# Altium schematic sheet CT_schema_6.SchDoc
size 364 x 245 mm
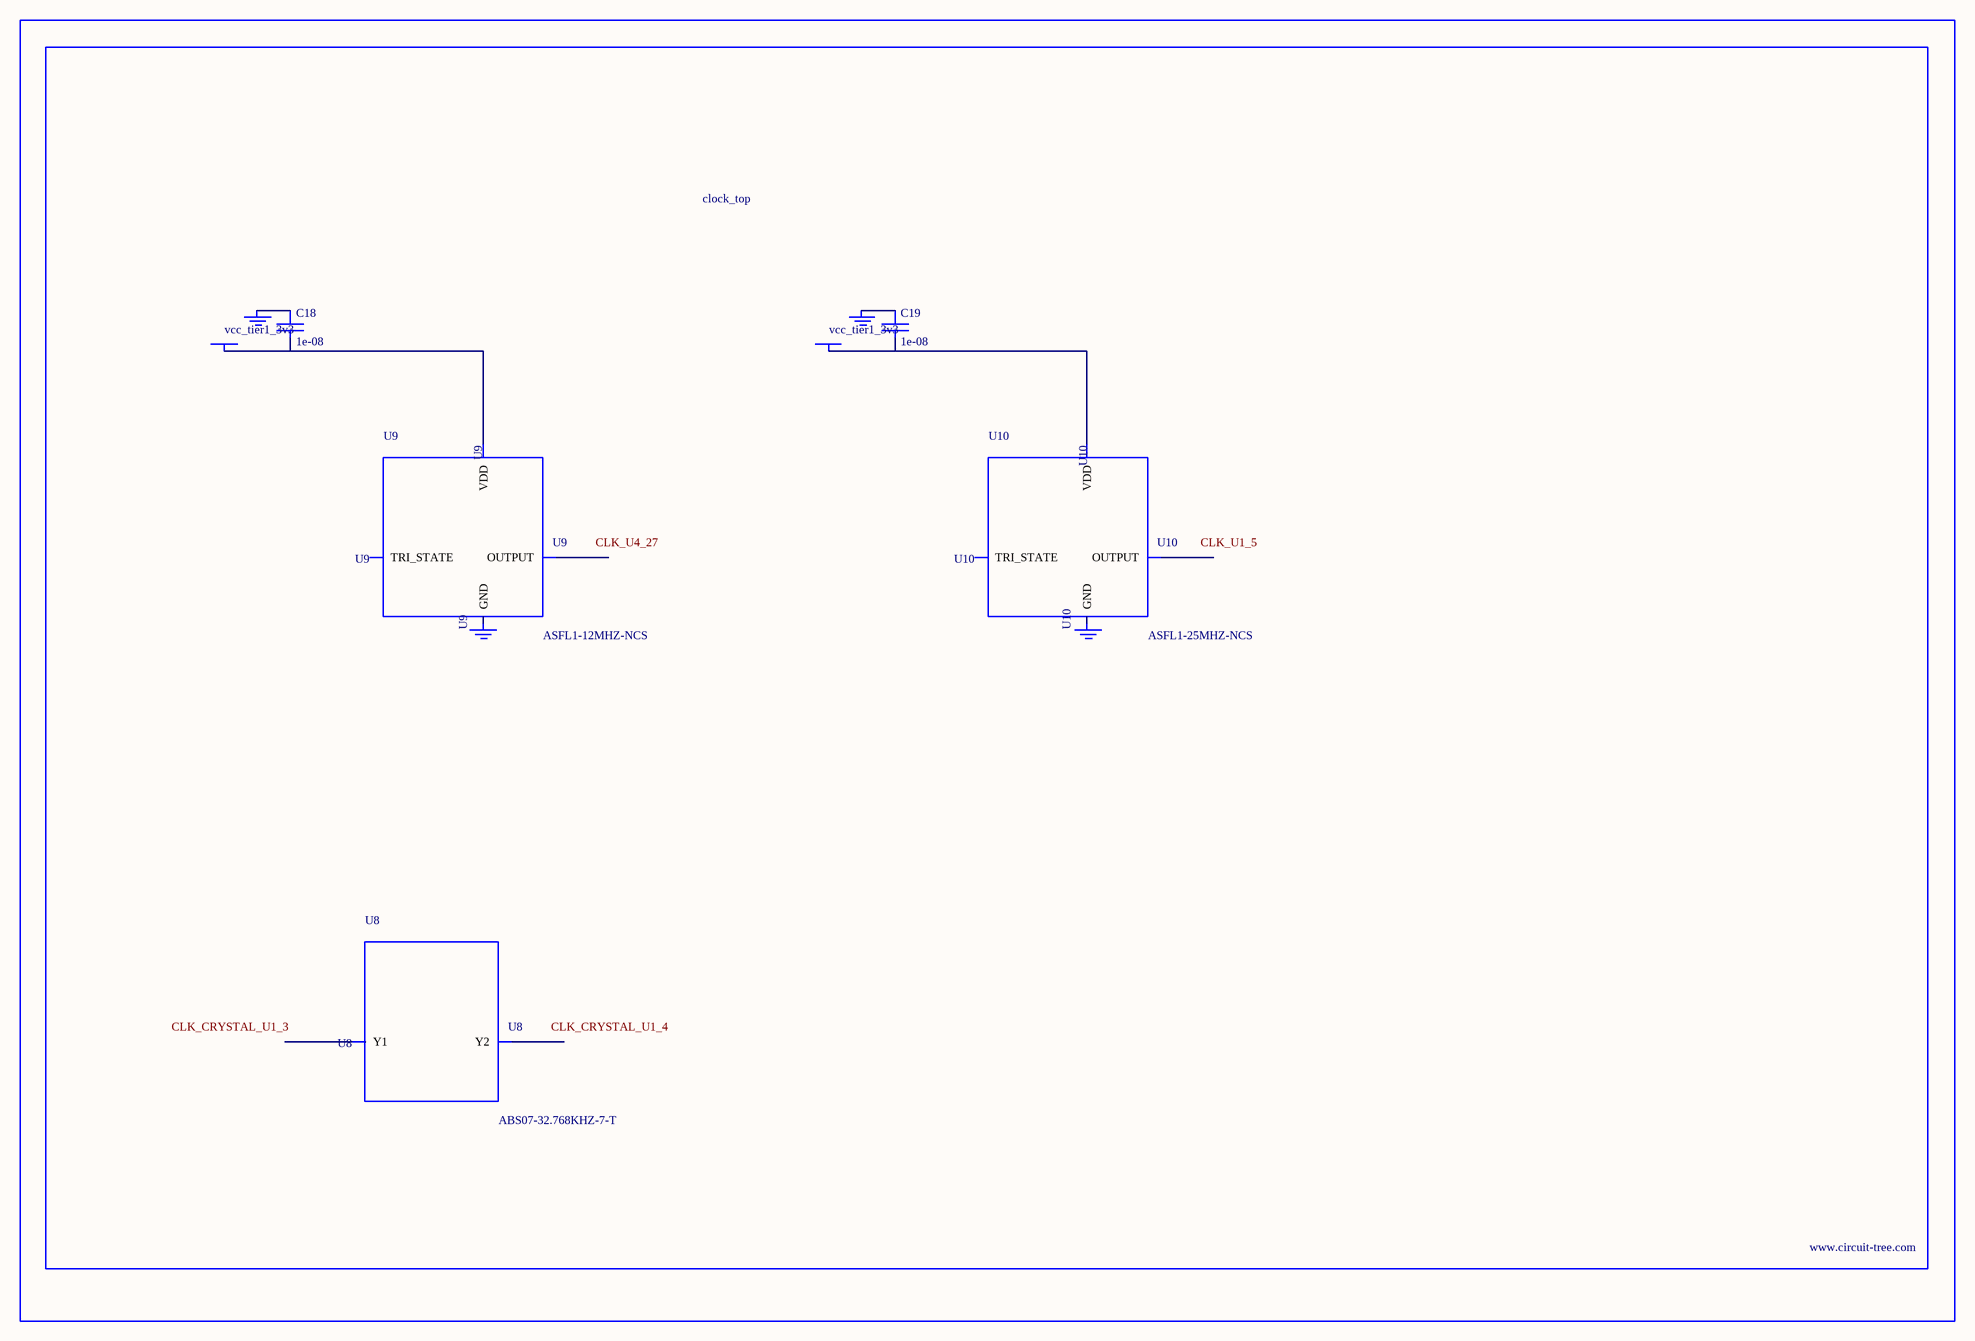
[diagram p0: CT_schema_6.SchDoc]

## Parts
BORDER5  (no value)
C18  1e-08  [C0402]
C19  1e-08  [C0402]
GND_INSTANCE_5_0  (no value)
GND_INSTANCE_5_1  (no value)
GND_INSTANCE_5_2  (no value)
GND_INSTANCE_5_3  (no value)
POWER_INSTANCE_5_0  vcc_tier1_3v3
POWER_INSTANCE_5_1  vcc_tier1_3v3
U8  ABS07-32.768KHZ-7-T  [ABS07-32.768KHZ-7-T]
U9  ASFL1-12MHZ-NCS  [ASFL1]
U10  ASFL1-25MHZ-NCS  [ASFL1]

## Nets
NetC18_1: C18.1 GND_INSTANCE_5_0.0(GND)
NetC18_2: C18.2 POWER_INSTANCE_5_0.0(PWR) U9.4(VDD)
NetC19_1: C19.1 GND_INSTANCE_5_2.0(GND)
NetC19_2: C19.2 POWER_INSTANCE_5_1.0(PWR) U10.4(VDD)

Not connected (* = marked no-connect by the designer): GND_INSTANCE_5_1 0(GND); GND_INSTANCE_5_3 0(GND); U8 1(Y1) 2(Y2); U9 1(TRI_STATE) 2(GND) 3(OUTPUT); U10 1(TRI_STATE) 2(GND) 3(OUTPUT)

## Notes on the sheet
- Labels drawn without touching a wire or pin: CLK_CRYSTAL_U1_3, CLK_CRYSTAL_U1_4, CLK_U1_5, CLK_U4_27

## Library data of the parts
BORDER5 = BORDER_PAGE5
C18 C19 = C0402C103K3RAC
GND_INSTANCE_5_0-GND_INSTANCE_5_3 = GND
POWER_INSTANCE_5_0 POWER_INSTANCE_5_1 = PWR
